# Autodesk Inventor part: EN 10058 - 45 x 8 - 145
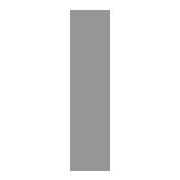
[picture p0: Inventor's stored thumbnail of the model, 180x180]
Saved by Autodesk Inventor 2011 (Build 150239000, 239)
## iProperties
_CCFamilyMember: 49
_CCFamilyDisplayName: DIN EN 10058 - Hot rolled flat steel bars for general purposes
_FrameMemberDoc: Frame Member File
_Version: 15.0.0
_GetPNFromCC: 1
Created: 2010-02
Part Number: EN 10058 - 45 x 8 - 145
Material: Steel, Mild
Description: flat steel bar 45*8
Document SubType Name: Modeling
Standard: DIN
Designer: PC
Standard Revision: 2004
Standards Organization: DIN
Language: en-US
Size Designation: 45 x 8
Categories: <MemberInstance><Categories><Category DisplayName="Structural Shapes" InternalName="089c4875-fa83-4c05-b084-43b9cc11f5ed" Mnemonic="GRDR"><CategoryParameter Dis
Stock Number: 45 x 8
Density: 7.86 g/cm^3
IsCustomPart: 1
G_L: 145.000 mm
G_W: 8.000 mm
G_H: 45.000 mm
Author: PC
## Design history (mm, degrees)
node "Start plane"
node "End plane"
sketch "Sketch"
  geometry: L1 (4, -22.5)-(-4, -22.5); L2 (-4, -22.5)-(-4, 22.5); L3 (-4, 22.5)-(4, 22.5); L4 (4, 22.5)-(4, -22.5); L5 (-6, 0)-(8, 0); L6 (0, -30)-(0, 40); L7 (0, 54)-(0, -44) reference; L8 (-9.2, 0)-(13.2, 0) reference
  constraints: 12 end point, 2 collinear, 2 parallel, 1 horizontal, 1 perpendicular
  dimensions: "d0" = 45 distance between parallel lines of L3 L1 (= G_W); "d1" = 8 distance between parallel lines of L4 L2 (= G_H); "d4" = 4 distance between parallel lines of L6 L4 (= 0.5 x d1); "d5" = 22.5 distance between parallel lines of L5 L3 (= 0.5 x d0)
extrude "Body" new body sketch "Sketch" stored distance "d2" = 145 (= G_L); taper "d3" = 0 deg
node "Driven Length"
  sketch "Sketch3"
    geometry: L1 (0, 0)-(10, 0) reference
    constraints: 2 end point, 1 horizontal
  workplane "Work Plane3"
  sketch "Sketch4"
    geometry: L1 (-2, 0)-(12, 0) reference; L2 (-2, 145)-(12, 145) reference
    dimensions: "d9" = 145 distance between parallel lines of L1 L2 (derived)
body "Solid1"
other parameters: "G_W" = 45 [user parameter; used in 1 equation term], "G_H" = 8 [user parameter; used in 1 equation term], "G_L" = 145 (= d9) [user parameter; used in 1 equation term], "G_OFFSET_START" = 0 [user parameter; used in 1 equation term], "G_OFFSET_END" = 0 [user parameter; used in 1 equation term], "d6" = 0 (computed from G_OFFSET_START), "d7" = 145 (= G_OFFSET_END + B_L), "B_L" = 145 [user parameter; used in 1 equation term], "d8" = 90 deg, "MAS" = 0.283 [user parameter]
